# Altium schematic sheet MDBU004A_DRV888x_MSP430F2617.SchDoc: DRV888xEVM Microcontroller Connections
size 431 x 279 mm; Date: Not shown in title block; ApprovedBy: Not shown in title block; CheckedBy: Not shown in title block; Author: Not shown in title block; CompanyName: Not shown in title block; DrawnBy: Rick Duncan; Engineer: Not shown in title block; Organization: Not shown in title block; Address1: Not shown in title block; Address2: Not shown in title block; Address3: Not shown in title block; Address4: Not shown in title block; DocumentNumber: 1; Revision: Use project parameter SCH_Rev; SheetNumber: 2; SheetTotal: 3; PageSetup: Record=PageOptions¦CenterHorizontal=True¦CenterVertical=True¦PrintScale=1.00¦XCorrection=1.00¦YCorrection=1.00¦PrintKind=0¦BorderSize=5000000¦LeftOffset=0¦BottomOffset=0¦Orientation=2¦PaperLength=1000¦PaperWidth=1000¦Scale=100¦PaperSource=15¦PrintQuality=-3¦MediaType=1¦DitherType=10¦PrintScaleMode=1¦PaperKind=Letter¦PaperIndex=1
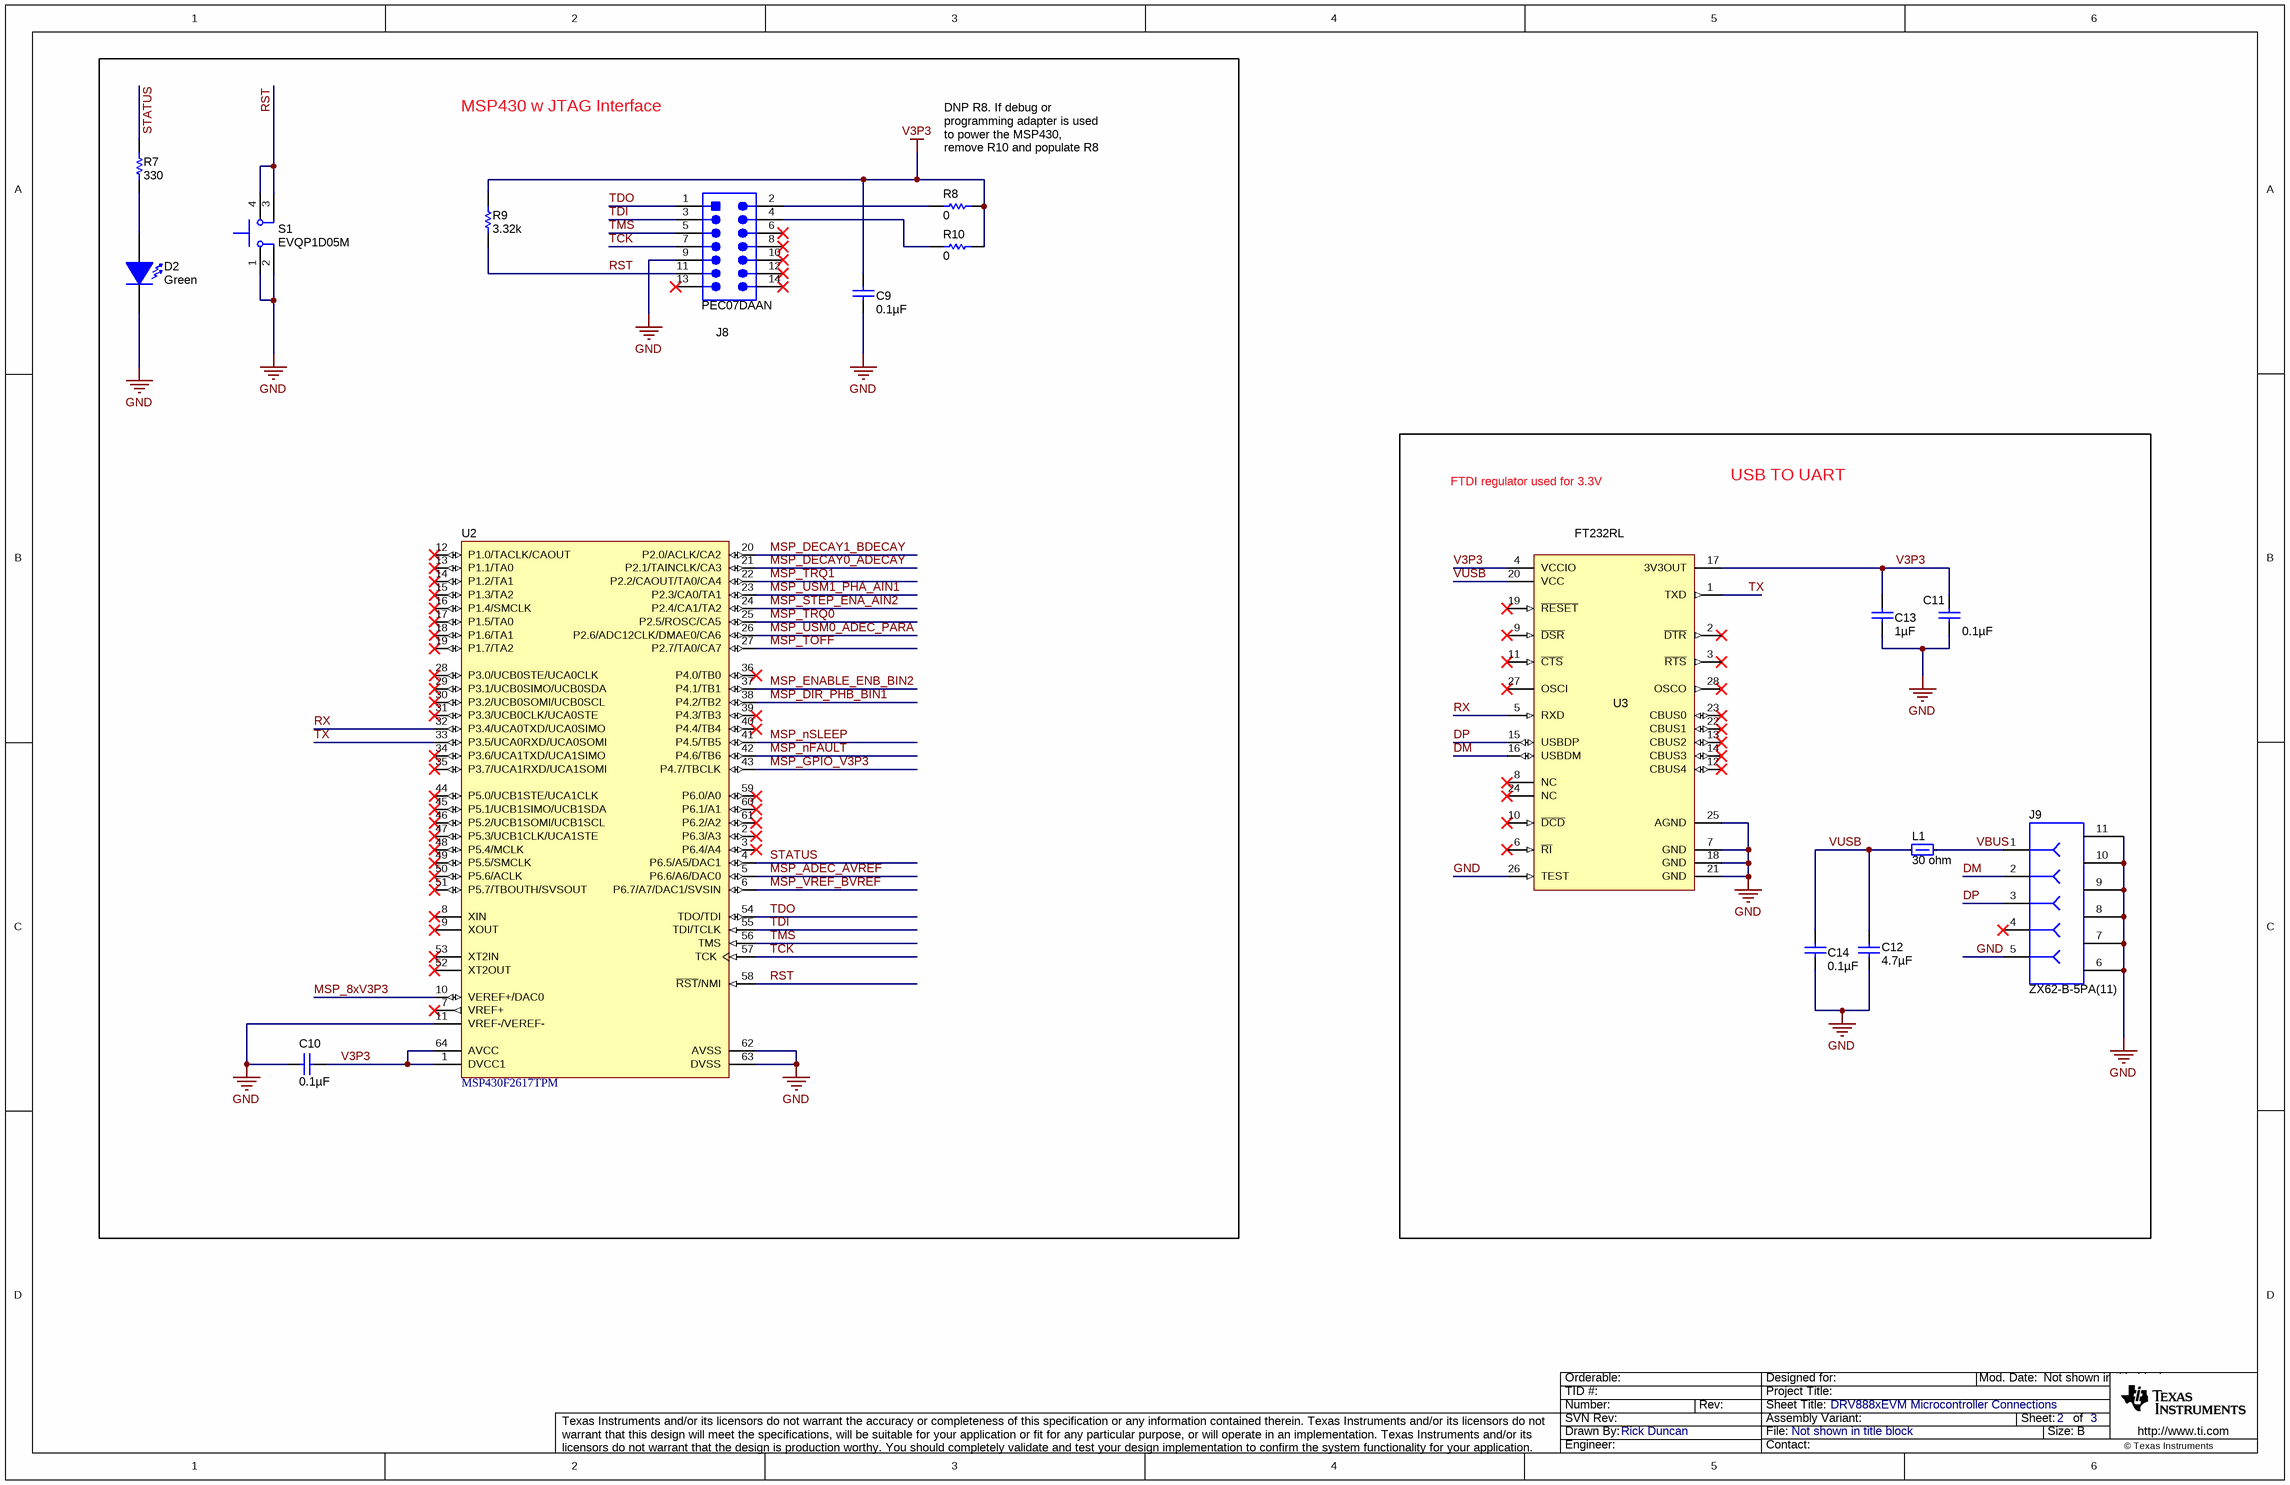
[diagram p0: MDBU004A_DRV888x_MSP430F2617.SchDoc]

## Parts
C9  ValueDisplayed: 0.1µF  [0402L]  (hidden comment: GRM155R61A104KA01D)
C10  ValueDisplayed: 0.1µF  [0402L]  (hidden comment: GRM155R61A104KA01D)
C11  ValueDisplayed: 0.1µF  [0402L]  (hidden comment: GRM155R61A104KA01D)
C12  ValueDisplayed: 4.7µF  [0603L]  (hidden comment: CGB3B1X5R1A475K055AC)
C13  ValueDisplayed: 1µF  [0402L]  (hidden comment: GRM155R61A105KE15D)
C14  ValueDisplayed: 0.1µF  [0402L]  (hidden comment: GRM155R61A104KA01D)
D2  value Green  [LED_LTST-C190]  (hidden comment: LTST-C190GKT)
J8  PEC07DAAN  [CONN_PEC07DAAN]
J9  ZX62-B-5PA(11)  [CONN_USB_micro_ZX62-B-5PA]
L1  value 30 ohm  [0805L]  (hidden comment: MMZ2012R300A)
R7  value 330  [0402L]  (hidden comment: CRCW0402330RJNED)
R8  value 0  [0402L]  (hidden comment: ERJ-2GE0R00X)
R9  value 3.32k  [0402L]  (hidden comment: CRCW04023K32FKED)
R10  value 0  [0402L]  (hidden comment: ERJ-2GE0R00X)
S1  EVQP1D05M  [SW_EVQxxx05M]
U2  MSP430F2617TPM  [PM0064A_L]
U3  FT232RL  [SSOP28_M]

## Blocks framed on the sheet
MSP430 w JTAG Interface: C9 C10 D2 J8 R7-R10 S1 U2
USB TO UART: C11-C14 J9 L1 U3

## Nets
GND: C9.2 C10.2 C11.2 C12.2 C13.2 C14.2 D2.2(K) J8.9 J9.5 J9.6 J9.7 J9.8 J9.9 J9.10 J9.11 S1.1 S1.2 U2.11(VREF-/VEREF-) U2.62(AVSS) U2.63(DVSS) U3.7(GND) U3.18(GND) U3.21(GND) U3.25(AGND) U3.26(TEST)
V3P3: C9.1 C10.1 C11.1 C13.1 R8.1 R9.2 R10.1 U2.1(DVCC1) U2.64(AVCC) U3.4(VCCIO) U3.17(3V3OUT)
DM: J9.2 U3.16(USBDM)
DP: J9.3 U3.15(USBDP)
MSP_8xV3P3: U2.10(VEREF+/DAC0)
MSP_ADEC_AVREF: U2.5(P6.6/A6/DAC0)
MSP_DECAY0_ADECAY: U2.21(P2.1/TAINCLK/CA3)
MSP_DECAY1_BDECAY: U2.20(P2.0/ACLK/CA2)
MSP_DIR_PHB_BIN1: U2.38(P4.2/TB2)
MSP_ENABLE_ENB_BIN2: U2.37(P4.1/TB1)
MSP_GPIO_V3P3: U2.43(P4.7/TBCLK)
MSP_nFAULT: U2.42(P4.6/TB6)
MSP_nSLEEP: U2.41(P4.5/TB5)
MSP_STEP_ENA_AIN2: U2.24(P2.4/CA1/TA2)
MSP_TOFF: U2.27(P2.7/TA0/CA7)
MSP_TRQ0: U2.25(P2.5/ROSC/CA5)
MSP_TRQ1: U2.22(P2.2/CAOUT/TA0/CA4)
MSP_USM0_ADEC_PARA: U2.26(P2.6/ADC12CLK/DMAE0/CA6)
MSP_USM1_PHA_AIN1: U2.23(P2.3/CA0/TA1)
MSP_VREF_BVREF: U2.6(P6.7/A7/DAC1/SVSIN)
RST: J8.11 R9.1 S1.3 S1.4 U2.58(~{RST}/NMI)
RX: U2.32(P3.4/UCA0TXD/UCA0SIMO) U3.5(RXD)
STATUS: R7.2 U2.4(P6.5/A5/DAC1)
TCK: J8.7 U2.57(TCK)
TDI: J8.3 U2.55(TDI/TCLK)
TDO: J8.1 U2.54(TDO/TDI)
TMS: J8.5 U2.56(TMS)
TX: U2.33(P3.5/UCA0RXD/UCA0SOMI) U3.1(TXD)
VBUS: J9.1 L1.2
VUSB: C12.1 C14.1 L1.1 U3.20(VCC)
NetD2_1: D2.1(A) R7.1
NetJ8_2: J8.2 R8.2
NetJ8_4: J8.4 R10.2

Not connected (* = marked no-connect by the designer): J8 6* 8* 10* 12* 13* 14*; J9 4*; U2 2(P6.3/A3)* 3(P6.4/A4)* 7(VREF+)* 8(XIN)* 9(XOUT)* 12(P1.0/TACLK/CAOUT)* 13(P1.1/TA0)* 14(P1.2/TA1)* 15(P1.3/TA2)* 16(P1.4/SMCLK)* 17(P1.5/TA0)* 18(P1.6/TA1)* 19(P1.7/TA2)* 28(P3.0/UCB0STE/UCA0CLK)* 29(P3.1/UCB0SIMO/UCB0SDA)* 30(P3.2/UCB0SOMI/UCB0SCL)* 31(P3.3/UCB0CLK/UCA0STE)* 34(P3.6/UCA1TXD/UCA1SIMO)* 35(P3.7/UCA1RXD/UCA1SOMI)* 36(P4.0/TB0)* 39(P4.3/TB3)* 40(P4.4/TB4)* 44(P5.0/UCB1STE/UCA1CLK)* 45(P5.1/UCB1SIMO/UCB1SDA)* 46(P5.2/UCB1SOMI/UCB1SCL)* 47(P5.3/UCB1CLK/UCA1STE)* 48(P5.4/MCLK)* 49(P5.5/SMCLK)* 50(P5.6/ACLK)* 51(P5.7/TBOUTH/SVSOUT)* 52(XT2OUT)* 53(XT2IN)* 59(P6.0/A0)* 60(P6.1/A1)* 61(P6.2/A2)*; U3 2(~{DTR})* 3(~{RTS})* 6(~{RI})* 8(NC)* 9(~{DSR})* 10(~{DCD})* 11(~{CTS})* 12(CBUS4)* 13(CBUS2)* 14(CBUS3)* 19(~{RESET})* 22(CBUS1)* 23(CBUS0)* 24(NC)* 27(OSCI)* 28(OSCO)*

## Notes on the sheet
- (near R8) DNP R8. If debug or programming adapter is used to power the MSP430, remove R10 and populate R8
- FTDI regulator used for 3.3V

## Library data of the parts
C9-C11 C14 = GRM155R61A104KA01D: CAP, CERM, 0.1 µF, 10 V, +/- 10%, X5R, 0402; Manufacturer: MuRata; Value: 0.1uF; Polarized: N; CompType: Capacitor; U/M: EA; Cap_F: 0.0000001; Tolerance_%: 10; Value1: Unknown; Value2: 10V; TaMin_C: -55; TaMax_C: 85; Cap_Case: 0402
C12 = CGB3B1X5R1A475K055AC: CAP, CERM, 4.7 µF, 10 V, +/- 10%, X5R, 0603; Manufacturer: TDK; Polarized: N; CompType: Capacitor; Value: 4.7uF; U/M: EA; Cap_F: 0.0000047; Tolerance_%: 10; Value1: Unknown; Value2: 10V; TaMin_C: -55; TaMax_C: 85; Cap_Case: 0603
C13 = GRM155R61A105KE15D: CAP, CERM, 1 µF, 10 V, +/- 10%, X5R, 0402; Manufacturer: MuRata; Value: 1uF; Polarized: N; CompType: Capacitor; U/M: EA; Cap_F: 0.000001; Tolerance_%: 10; Value1: Unknown; Value2: 10V; TaMin_C: -55; TaMax_C: 85; Cap_Case: 0402
D2 = LTST-C190GKT: LED, Green, SMD; Manufacturer: Lite-On; Vf_V: 2.1; Value2: 2.1V; Io_A: 0.02; Power_TotalModule: 0.1; Value1: 0.1W; U/M: EA
J8 = PEC07DAAN: Header, 100mil, 7x2, Tin, TH; Manufacturer: Sullins Connector Solutions; SymbolCreator: a0412235; U/M: EA
J9 = ZX62-B-5PA(11): Connector, Receptacle, Micro-USB Type B, R/A, Bottom Mount SMT; Manufacturer: Hirose Electric Co. Ltd.; SymbolCreator: a0411947; U/M: EA
L1 = MMZ2012R300A: Ferrite Bead, 30 ohm @ 100 MHz, 1.5 A, 0805; Manufacturer: TDK; Imax_A: 1.5; DCR_ohm: 0.05; Value1: 0.05 ohm; Value2: 1.5A; ZTyp@100MHz_Ohm: 30
R7 = CRCW0402330RJNED: RES, 330, 5%, 0.063 W, 0402; Manufacturer: Vishay-Dale; CompType: Resistor; Value_Code: 330R; Tolerance_%: 5; Power_W: 0.063; Value2: 0.063W; VDC_V: 50; TempCo: 200 ppm/C; EIA_Code: E24; U/M: EA
R8 R10 = ERJ-2GE0R00X: RES, 0, 5%, 0.063 W, 0402; Manufacturer: Panasonic; CompType: Resistor; Value_Code: 0000; Tolerance_%: 5; Power_W: 0.063; Value2: 0.063W; VDC_V: 50; TempCo: 600 ppm/C; EIA_Code: E24; U/M: EA
R9 = CRCW04023K32FKED: RES, 3.32 k, 1%, 0.063 W, 0402; Manufacturer: Vishay-Dale; CompType: Resistor; Res_ohm: 3320; Value_Code: 3k32; Tolerance_%: 1; Power_W: 0.063; Value2: 0.063W; VDC_V: 50; TempCo: 100 ppm/C; EIA_Code: E96; U/M: EA
S1 = EVQP1D05M: Switch, Tactile, SPST-NO, 0.05A, 12V, SMT; Manufacturer: Panasonic; SymbolCreator: a0799628; VDC_V: 12; SwitchFunction: Off-Mom; PositionCount: 1; CurrentRating_mA: 50
U2 = MSP430F2617TPM: 16 MHz Mixed Signal Microcontroller with 92 KB Flash, 8192 B SRAM and 48 GPIOs, -40 to 105 degC, 64-pin QFP (PM), Green (RoHS & no Sb/Br); Manufacturer: Texas Instruments; Alternate PartNumber: Equivalent; ADC: 12-bit SAR; ADC Channels: 8; Brown Out Reset: Yes; DMA: 3; Flash(KB): 92; Frequency(MHz): 16; GPIO: 48; Multiplier: 16x16; Pin/Package: 64LQFP; SRAM(B): 8192; SubFamily: 2 Series, Extended Temp; Timers - 16-bit: 2
U3 = FT232RL: USB to Serial UART, SSOP28; Manufacturer: FTDI; SymbolCreator: x0208326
